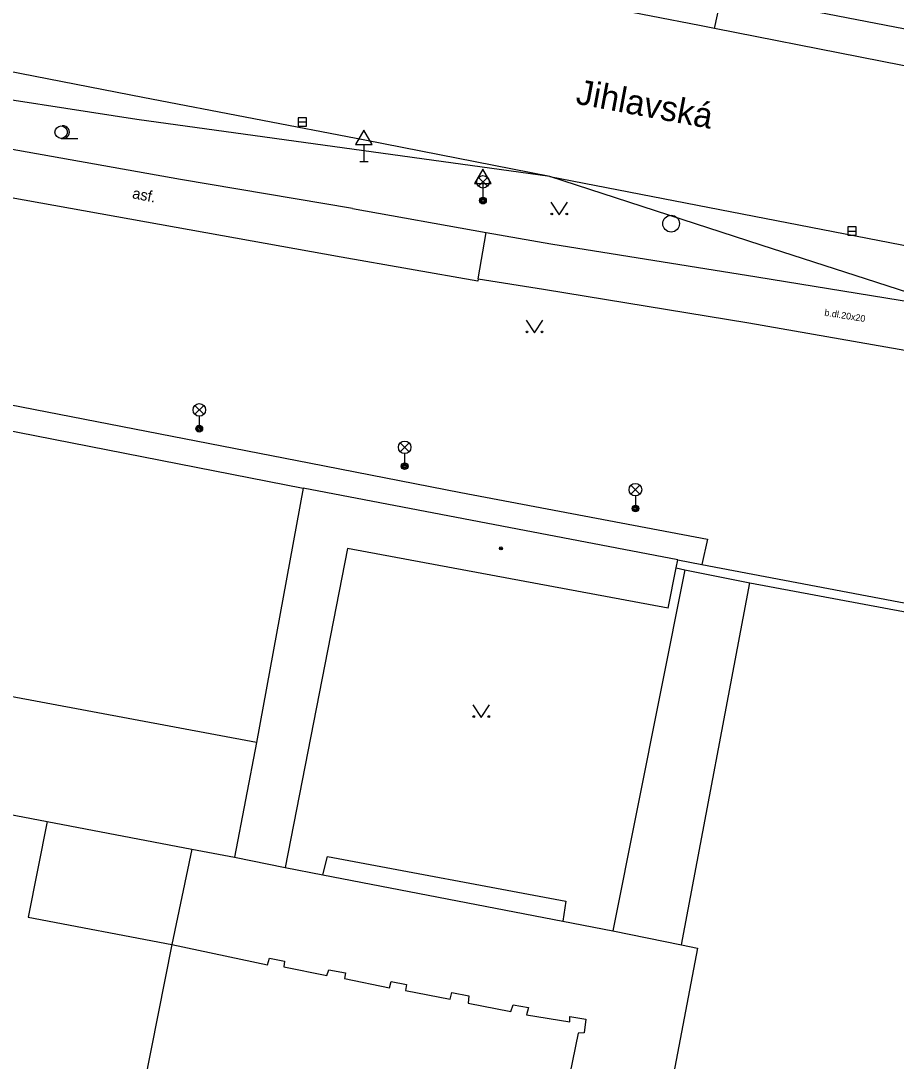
# Model space of a CAD drawing. Extents: x -599951 to -598963, y -1164095 to -1162939.
# Drawn here: x -599783 to -599730.6, y -1163123.5 to -1163061.2 of the extents above; entities that cross this region are included whole.
import ezdxf

# ---------------------------------------------------------------- set-up
doc = ezdxf.new("R2010")
doc.units = 0
for name, color, linetype in [('Level 10', 7, 'Continuous'), ('Level 11', 7, 'Continuous'), ('Level 27', 7, 'Continuous'), ('Level 33', 7, 'Continuous'), ('Level 34', 7, 'Continuous'), ('Level 36', 7, 'Continuous'), ('Level 39', 7, 'Continuous'), ('Level 40', 7, 'Continuous'), ('Level 49', 7, 'Continuous'), ('Level 5', 7, 'Continuous'), ('Level 7', 7, 'Continuous')]:
    doc.layers.add(name, color=color, linetype=linetype)

msp = doc.modelspace()

# ---------------------------------------------------------------- linework, layer by layer
at = {"layer": 'Level 10'}
for points in [[(-599742.38, -1163061.44), (-599756.85, -1163058.63), (-599804.09, -1163049.47)], [(-599762.43, -1163068.31), (-599775.73, -1163065.76), (-599786.29, -1163063.7), (-599798.11, -1163061.44)], [(-599685.84, -1163072.41), (-599690.72, -1163071.47), (-599700.76, -1163069.54), (-599724.04, -1163065.06), (-599741.48, -1163061.62), (-599742.38, -1163061.44)], [(-599751.34, -1163070.49), (-599762.43, -1163068.31)], [(-599693.5, -1163081.88), (-599694.51, -1163081.86), (-599707.02, -1163082.03), (-599707.51, -1163081.89), (-599707.99, -1163081.75), (-599727.57, -1163077.94), (-599728.6, -1163077.86), (-599738.68, -1163074.59), (-599751.34, -1163070.49)]]:
    msp.add_lwpolyline(points, dxfattribs=at)
at = {"layer": 'Level 11'}
for points in [[(-599741.48, -1163061.62), (-599741.03, -1163059.5), (-599713.42, -1163064.86), (-599688.34, -1163069.74), (-599687.57, -1163069.89), (-599685.41, -1163070.31), (-599685.73, -1163071.88), (-599685.84, -1163072.41)], [(-599776.09, -1163067.08), (-599799.29, -1163063.48)], [(-599763.17, -1163072.4), (-599773.46, -1163070.66), (-599799.58, -1163066.01)], [(-599751.34, -1163070.49), (-599776.09, -1163067.08)], [(-599763.84, -1163075.32), (-599800.83, -1163068.66)], [(-599751.34, -1163070.49), (-599717.41, -1163077.07), (-599692.73, -1163081.88)], [(-599763.17, -1163072.4), (-599755.16, -1163073.84)], [(-599755.64, -1163076.61), (-599755.16, -1163073.84)], [(-599755.16, -1163073.84), (-599751.29, -1163074.51)], [(-599751.29, -1163074.51), (-599738.95, -1163076.5), (-599728.65, -1163078.18)], [(-599755.66, -1163076.76), (-599763.84, -1163075.32)], [(-599755.64, -1163076.61), (-599755.66, -1163076.76)], [(-599755.64, -1163076.61), (-599751.73, -1163077.23), (-599739.43, -1163079.25), (-599719.15, -1163082.81), (-599719.27, -1163083.6), (-599713.63, -1163084.69), (-599713.46, -1163083.92), (-599710.91, -1163084.41), (-599710.13, -1163084.56), (-599708.53, -1163084.87), (-599693.98, -1163088.66), (-599691.95, -1163089.08), (-599691.17, -1163089.24)], [(-599803.22, -1163080.35), (-599765.76, -1163087.64), (-599756.68, -1163089.42), (-599741.9, -1163092.2), (-599742.25, -1163093.72)], [(-599803.47, -1163081.83), (-599766.12, -1163089.15)], [(-599743.26, -1163094.05), (-599747.58, -1163115.67)], [(-599743.77, -1163093.93), (-599743.26, -1163094.05)], [(-599743.26, -1163094.05), (-599739.36, -1163094.82)], [(-599743.46, -1163116.51), (-599739.36, -1163094.82)], [(-599781.45, -1163109.12), (-599782.58, -1163114.84), (-599773.98, -1163116.49)], [(-599772.79, -1163110.77), (-599773.98, -1163116.49)], [(-599764.94, -1163112.32), (-599764.66, -1163111.21), (-599750.38, -1163113.9), (-599750.57, -1163115.09)], [(-599773.98, -1163116.49), (-599776.49, -1163129.08)], [(-599773.98, -1163116.49), (-599768.25, -1163117.7), (-599768.13, -1163117.31), (-599767.23, -1163117.49), (-599767.27, -1163117.83), (-599764.7, -1163118.35), (-599764.58, -1163118.01), (-599763.58, -1163118.19), (-599763.64, -1163118.53), (-599760.94, -1163119.08), (-599760.85, -1163118.71), (-599759.94, -1163118.88), (-599759.99, -1163119.25), (-599757.31, -1163119.76), (-599757.21, -1163119.37), (-599756.19, -1163119.57), (-599756.24, -1163119.99), (-599753.68, -1163120.5), (-599753.54, -1163120.1), (-599752.62, -1163120.26), (-599752.75, -1163120.69), (-599750.15, -1163121.12), (-599750.14, -1163120.8), (-599749.18, -1163120.96), (-599749.29, -1163121.78), (-599749.65, -1163121.8), (-599750.33, -1163125.11)]]:
    msp.add_lwpolyline(points, dxfattribs=at)
at = {"layer": 'Level 27'}
for p, q in [((-599766.41, -1163067.22), (-599765.91, -1163067.22)), ((-599733.5, -1163073.75), (-599733, -1163073.75))]:
    msp.add_line(p, q, dxfattribs=at)
for points in [[(-599766.41, -1163067.47), (-599765.91, -1163067.47), (-599765.91, -1163066.97), (-599766.41, -1163066.97)], [(-599733.5, -1163074), (-599733, -1163074), (-599733, -1163073.5), (-599733.5, -1163073.5)]]:
    msp.add_lwpolyline(points, close=True, dxfattribs=at)
msp.add_circle((-599744.08, -1163073.31), 0.5, dxfattribs=at)
at = {"layer": 'Level 33'}
for p, q in [((-599755.615, -1163071.07), (-599755.085, -1163070.54)), ((-599755.615, -1163070.54), (-599755.085, -1163071.07)), ((-599755.35, -1163071.18), (-599755.35, -1163071.93)), ((-599772.605, -1163084.73), (-599772.075, -1163084.2)), ((-599772.605, -1163084.2), (-599772.075, -1163084.73)), ((-599772.34, -1163084.84), (-599772.34, -1163085.59)), ((-599760.305, -1163086.97), (-599759.775, -1163086.44)), ((-599760.305, -1163086.44), (-599759.775, -1163086.97)), ((-599760.04, -1163087.08), (-599760.04, -1163087.83)), ((-599746.485, -1163089.51), (-599745.955, -1163088.98)), ((-599746.485, -1163088.98), (-599745.955, -1163089.51)), ((-599746.22, -1163089.62), (-599746.22, -1163090.37))]:
    msp.add_line(p, q, dxfattribs=at)
for centre, radius in [((-599755.35, -1163070.805), 0.375), ((-599755.35, -1163071.93), 0.2), ((-599755.35, -1163071.93), 0.145), ((-599755.35, -1163071.93), 0.0876), ((-599772.34, -1163084.465), 0.375), ((-599772.34, -1163085.59), 0.2), ((-599772.34, -1163085.59), 0.145), ((-599772.34, -1163085.59), 0.0876), ((-599760.04, -1163086.705), 0.375), ((-599760.04, -1163087.83), 0.2), ((-599760.04, -1163087.83), 0.145), ((-599760.04, -1163087.83), 0.0876), ((-599746.22, -1163089.245), 0.375), ((-599746.22, -1163090.37), 0.2), ((-599746.22, -1163090.37), 0.145), ((-599746.22, -1163090.37), 0.0876)]:
    msp.add_circle(centre, radius, dxfattribs=at)
at = {"layer": 'Level 34'}
for p, q in [((-599762.48, -1163068.572), (-599762.48, -1163069.59)), ((-599762.73, -1163069.59), (-599762.23, -1163069.59)), ((-599755.35, -1163070.912), (-599755.35, -1163071.93))]:
    msp.add_line(p, q, dxfattribs=at)
for points in [[(-599762.98, -1163068.572), (-599761.98, -1163068.572), (-599762.48, -1163067.706)], [(-599755.85, -1163070.912), (-599754.85, -1163070.912), (-599755.35, -1163070.046)]]:
    msp.add_lwpolyline(points, close=True, dxfattribs=at)
at = {"layer": 'Level 36'}
msp.add_line((-599780.61, -1163068.205), (-599779.61, -1163068.205), dxfattribs=at)
for points in [[(-599751.28, -1163072.03), (-599750.78, -1163072.78), (-599750.28, -1163072.03)], [(-599752.76, -1163079.09), (-599752.26, -1163079.84), (-599751.76, -1163079.09)], [(-599755.95, -1163102.13), (-599755.45, -1163102.88), (-599754.95, -1163102.13)]]:
    msp.add_lwpolyline(points, dxfattribs=at)
for centre, radius in [((-599780.61, -1163067.83), 0.375), ((-599751.23, -1163072.73), 0.05), ((-599750.331, -1163072.73), 0.05), ((-599752.71, -1163079.79), 0.05), ((-599751.811, -1163079.79), 0.05), ((-599755.9, -1163102.83), 0.05), ((-599755.001, -1163102.83), 0.05)]:
    msp.add_circle(centre, radius, dxfattribs=at)
msp.add_arc((-599780.485, -1163067.83), 0.375, 260.40593, 99.59407, dxfattribs=at)
at = {"layer": 'Level 39'}
for radius in [0.09, 0.0398]:
    msp.add_circle((-599754.28, -1163092.76), radius, dxfattribs=at)
at = {"layer": 'Level 5'}
for points in [[(-599766.12, -1163089.15), (-599768.92, -1163104.39)], [(-599743.67, -1163093.45), (-599766.12, -1163089.15)], [(-599763.47, -1163092.76), (-599767.2, -1163111.88)], [(-599744.25, -1163096.35), (-599763.47, -1163092.76)], [(-599743.77, -1163093.93), (-599743.67, -1163093.45)], [(-599744.25, -1163096.35), (-599743.77, -1163093.93)], [(-599768.92, -1163104.39), (-599806.41, -1163097.38)], [(-599768.92, -1163104.39), (-599770.24, -1163111.26)], [(-599788.98, -1163107.68), (-599781.45, -1163109.12)], [(-599781.45, -1163109.12), (-599772.79, -1163110.77)], [(-599772.79, -1163110.77), (-599770.24, -1163111.26)], [(-599770.24, -1163111.26), (-599767.2, -1163111.88)], [(-599767.2, -1163111.88), (-599764.94, -1163112.32)], [(-599764.94, -1163112.32), (-599750.57, -1163115.09)], [(-599750.57, -1163115.09), (-599747.58, -1163115.67)], [(-599747.58, -1163115.67), (-599743.46, -1163116.51)], [(-599742.51, -1163116.7), (-599744.1, -1163125.09)], [(-599743.46, -1163116.51), (-599742.51, -1163116.7)]]:
    msp.add_lwpolyline(points, dxfattribs=at)
at = {"layer": 'Level 7'}
for points in [[(-599743.67, -1163093.45), (-599742.25, -1163093.72)], [(-599742.25, -1163093.72), (-599693.57, -1163102.95), (-599687.63, -1163104.15)], [(-599739.36, -1163094.82), (-599716.47, -1163099.09), (-599694.04, -1163103.27), (-599697.97, -1163123.09), (-599698.27, -1163124.58), (-599703.63, -1163123.67), (-599703.81, -1163124.32)]]:
    msp.add_lwpolyline(points, dxfattribs=at)

# ---------------------------------------------------------------- texts
at = {"layer": 'Level 40'}
for s, height, rotation, p in [('asf.', 0.65, 348.83, (-599776.39, -1163071.78)), ('b.dl.20x20', 0.4, 351, (-599734.92, -1163078.82))]:
    msp.add_text(s, height=height, rotation=rotation, dxfattribs=at).set_placement(p)
at = {"layer": 'Level 49'}
msp.add_text('Jihlavská', height=1.5, rotation=349.44, dxfattribs=at).set_placement((-599749.85, -1163066.12))

doc.saveas('drawing.dxf')
